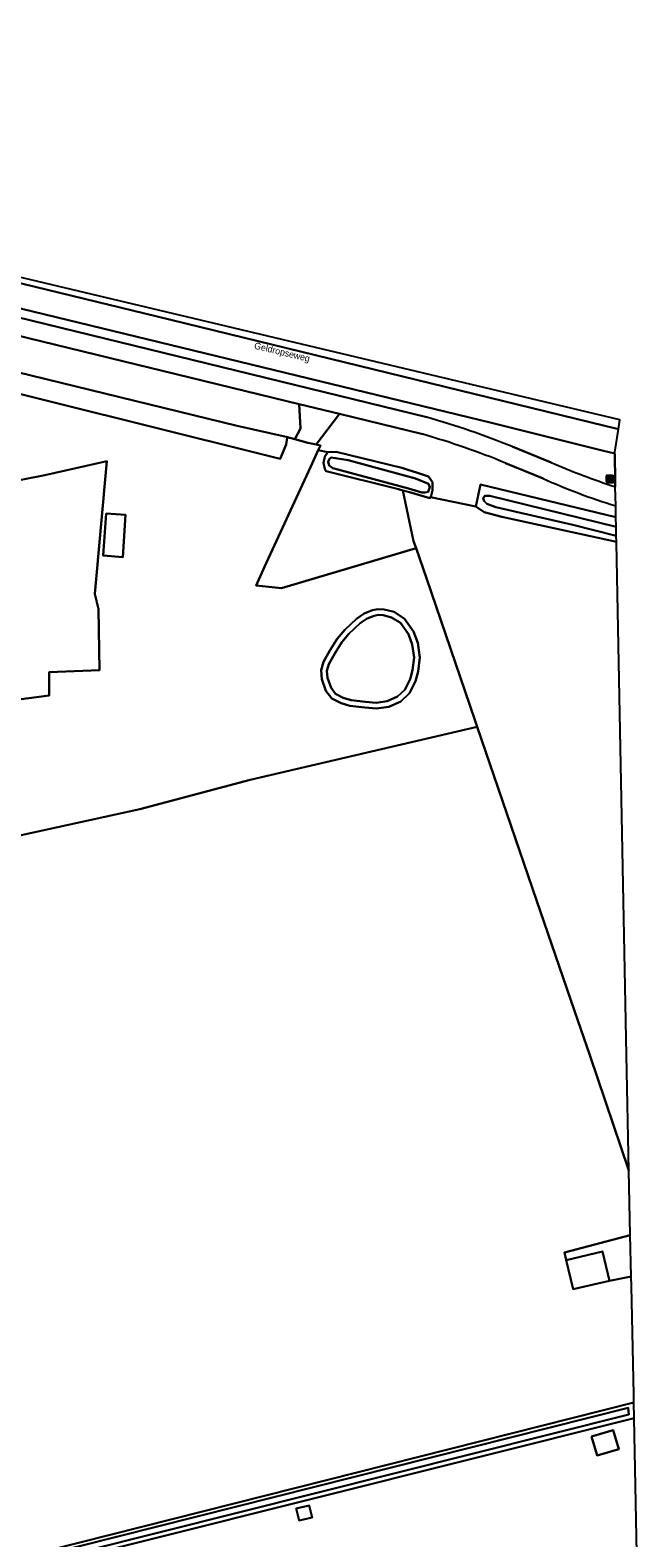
# Model space of a CAD drawing. Extents: x 163859 to 164644, y 379566 to 382155.
# Drawn here: x 164506.5 to 164599.2, y 381926.9 to 382155.2 of the extents above; entities that cross this region are included whole.
import ezdxf

# ---------------------------------------------------------------- set-up
doc = ezdxf.new("R2010")
doc.units = 0
for name, color, linetype in [('IMGEO_Berm_groen', 7, 'Continuous'), ('IMGEO_Erf', 7, 'Continuous'), ('IMGEO_Fietspad_gesloten', 7, 'Continuous'), ('IMGEO_Grasland_agrarisch', 7, 'Continuous'), ('IMGEO_Groenvoorziening', 7, 'Continuous'), ('IMGEO_Hek', 7, 'Continuous'), ('IMGEO_Lichtmast', 7, 'Continuous'), ('IMGEO_Loofbos', 7, 'Continuous'), ('IMGEO_Meer_plas_ven_vijver', 7, 'Continuous'), ('IMGEO_Oever', 7, 'Continuous'), ('IMGEO_Openbare_ruimte_label', 7, 'Continuous'), ('IMGEO_Pand', 7, 'Continuous'), ('IMGEO_Rijbaan_lokaal_onverhard', 7, 'Continuous'), ('IMGEO_Rijbaan_regionaal_gesloten', 7, 'Continuous'), ('IMGEO_Sloot', 7, 'Continuous'), ('IMGEO_Waterloop', 7, 'Continuous')]:
    doc.layers.add(name, color=color, linetype=linetype)

msp = doc.modelspace()

# ---------------------------------------------------------------- linework, layer by layer
at = {"layer": 'IMGEO_Berm_groen'}
msp.add_lwpolyline([(164595.15, 382087.13), (164595.08, 382091.04), (164595.08, 382090.8), (164595.15, 382087.13), (164595.15, 382087.13)], dxfattribs=at)
msp.add_lwpolyline([(164595.17, 382086.08), (164595.15, 382087.13), (164595.15, 382087.13)], close=True, dxfattribs=at)
at = {"layer": 'IMGEO_Erf'}
for points in [[(164503.08, 382032.86), (164523.11, 382037.28), (164539.85, 382041.68), (164574.25, 382049.73), (164573.89, 382050.78), (164566.54, 382072.23), (164564.98, 382076.78), (164544.61, 382070.72), (164540.74, 382071.15), (164542.03, 382073.97), (164548.98, 382089.07), (164550.17, 382091.64), (164550.48, 382092.32), (164549.84, 382092.47), (164548.6, 382092.76), (164546.64, 382093.3), (164545.32, 382093.66), (164545.44, 382093.5), (164545.3, 382092.48), (164544.39, 382090.34), (164522.31, 382095.81), (164513.2, 382098.08), (164500, 382101.39)], [(164489.95, 382084.16), (164508.72, 382087.84), (164518.12, 382089.97), (164516.34, 382069.87), (164516.85, 382067.53), (164517.02, 382058.31), (164509.39, 382058.02), (164509.38, 382054.47), (164503.23, 382053.66)]]:
    msp.add_lwpolyline(points, dxfattribs=at)
for points in [[(164518.05, 382082.03), (164520.97, 382081.81), (164520.54, 382075.41), (164517.58, 382075.67)], [(164560.15, 382067.52), (164561.64, 382067.12), (164563.24, 382066.11), (164564.61, 382064.19), (164565.24, 382062.43), (164565.55, 382060.24), (164565.31, 382058.13), (164564.88, 382056.65), (164563.98, 382054.81), (164562.65, 382053.56), (164560.86, 382052.78), (164558.98, 382052.5), (164557.22, 382052.66), (164554.95, 382052.89), (164553.62, 382053.32), (164552.22, 382054.03), (164551.32, 382055.2), (164550.69, 382056.96), (164550.58, 382058.29), (164550.97, 382059.58), (164551.9, 382061.3), (164553.04, 382063.06), (164554.17, 382064.43), (164555.97, 382066.11), (164557.14, 382066.89), (164558.36, 382067.4), (164559.18, 382067.55)], [(164597.57, 381966.47), (164597.43, 381972.77), (164587.47, 381970.11), (164587.73, 381968.98), (164593.24, 381970.26), (164594.27, 381965.83), (164597.57, 381966.47)]]:
    msp.add_lwpolyline(points, close=True, dxfattribs=at)
at = {"layer": 'IMGEO_Fietspad_gesloten'}
for points in [[(164351.79, 382149.02), (164352.26, 382146.27), (164358.29, 382144.8), (164362.68, 382143.73), (164380.09, 382139.4), (164383.9, 382138.46), (164391.87, 382136.53), (164462.95, 382119.3), (164479.66, 382115.15), (164500, 382110.11), (164547.27, 382098.59), (164553.37, 382097.11), (164566.02, 382094.03)], [(164566.61, 382096.62), (164500, 382112.87), (164480.06, 382117.73), (164432.23, 382129.4), (164397.28, 382137.92), (164390.72, 382139.52), (164384.51, 382141.04), (164380.7, 382141.97), (164360.68, 382146.85), (164351.79, 382149.02)], [(164585.46, 382089.75), (164579.54, 382092.17)], [(164578.55, 382089.67), (164584.23, 382087.34)], [(164595.23, 382083.2), (164595.17, 382086.08)]]:
    msp.add_lwpolyline(points, dxfattribs=at)
for centre, radius, start, end in [((164532.11, 381975.37), 126.06, 67.8989, 74.1185), ((164534.05, 381981.81), 116.68, 67.5816, 74.1012), ((164631.62, 382197.16), 116.91, 246.7456, 251.8362), ((164621.56, 382169.88), 90.59, 245.6621, 253.1015)]:
    msp.add_arc(centre, radius, start, end, dxfattribs=at)
at = {"layer": 'IMGEO_Grasland_agrarisch'}
for points in [[(164503.23, 382053.66), (164509.38, 382054.47), (164509.39, 382058.02), (164517.02, 382058.31), (164516.85, 382067.53), (164516.34, 382069.87), (164518.12, 382089.97), (164508.72, 382087.84), (164489.95, 382084.16)], [(164500, 381922.69), (164597.99, 381947.39), (164597.96, 381948.63), (164597.6, 381965), (164597.57, 381966.47), (164597.57, 381966.47), (164594.27, 381965.83), (164588.76, 381964.55), (164587.73, 381968.98), (164587.47, 381970.11), (164597.43, 381972.77), (164597.22, 381982.52), (164591.3, 382000), (164588.99, 382006.72), (164583.24, 382023.49), (164574.25, 382049.73), (164539.85, 382041.68), (164523.11, 382037.28), (164503.08, 382032.86)]]:
    msp.add_lwpolyline(points, dxfattribs=at)
at = {"layer": 'IMGEO_Groenvoorziening'}
for points in [[(164595.08, 382091.12), (164593.39, 382091.53), (164576.43, 382095.76), (164500, 382114.28), (164481.27, 382118.87), (164480.06, 382117.73), (164500, 382112.87), (164566.61, 382096.62)], [(164566.02, 382094.03), (164553.37, 382097.11), (164549.84, 382092.47), (164550.48, 382092.32), (164550.17, 382091.64), (164551.6, 382091.31), (164552.87, 382091.36), (164562.82, 382088.96), (164563.57, 382088.71), (164565.2, 382088.19), (164566.87, 382087.63), (164567.45, 382086.76), (164567.48, 382085.57), (164567.29, 382084.7), (164567.18, 382084.52), (164574.03, 382083.08), (164574.74, 382086.41), (164595.26, 382081.49), (164595.23, 382083.2)], [(164579.54, 382092.17), (164585.46, 382089.75)], [(164584.23, 382087.34), (164578.55, 382089.67)], [(164595.17, 382086.08), (164595.15, 382087.13), (164595.08, 382090.8), (164595.08, 382091.04), (164595.08, 382091.12)]]:
    msp.add_lwpolyline(points, dxfattribs=at)
for points in [[(164547.27, 382098.59), (164500, 382110.11), (164479.66, 382115.15), (164478.89, 382111.96), (164478.13, 382111.27), (164477.07, 382107.14), (164479.82, 382106.45), (164479.77, 382107.13), (164480.07, 382109.25), (164500, 382104.57), (164537.87, 382095.33), (164545.32, 382093.66), (164546.64, 382093.3), (164547.48, 382094.92)], [(164562.99, 382085.54), (164562.34, 382085.73), (164551.38, 382088.47), (164551.18, 382088.77), (164550.97, 382089.72), (164551.18, 382090.67), (164551.6, 382091.31), (164550.17, 382091.64), (164548.98, 382089.07), (164542.03, 382073.97), (164540.74, 382071.15), (164544.61, 382070.72), (164564.98, 382076.78), (164564.61, 382077.84)], [(164598.04, 381945.02), (164500, 381920.51), (164396.41, 381894.6), (164400.28, 381877.79), (164404.82, 381857.96), (164412.31, 381825.45), (164500, 381853.89), (164599.19, 381886.07)], [(164591.58, 381942.26), (164594.85, 381943.22), (164595.69, 381940.36), (164592.42, 381939.39)], [(164546.84, 381931.35), (164548.8, 381931.82), (164549.24, 381930.01), (164547.28, 381929.54)]]:
    msp.add_lwpolyline(points, close=True, dxfattribs=at)
for centre, radius, start, end in [((164532.11, 381975.37), 126.06, 67.8989, 74.1185), ((164534.05, 381981.81), 116.68, 67.5816, 74.1012), ((164631.62, 382197.16), 116.91, 246.7456, 251.8362), ((164621.56, 382169.88), 90.59, 245.6621, 253.1015)]:
    msp.add_arc(centre, radius, start, end, dxfattribs=at)
at = {"layer": 'IMGEO_Hek'}
for points in [[(164597.22, 381982.52), (164591.3, 382000)], [(164395.98, 381896.47), (164398.12, 381897.01), (164500, 381922.69), (164597.99, 381947.39)], [(164598.04, 381945.02), (164500, 381920.51), (164396.41, 381894.6)]]:
    msp.add_lwpolyline(points, dxfattribs=at)
at = {"layer": 'IMGEO_Lichtmast'}
for p, q in [((164593.81, 382086.9), (164593.81, 382087.7)), ((164593.81, 382087.7), (164593.81, 382086.9)), ((164593.91, 382087.8), (164594.69, 382087.8)), ((164594.69, 382087.8), (164593.91, 382087.8)), ((164593.92, 382086.83), (164593.92, 382087.63)), ((164593.92, 382087.63), (164593.92, 382086.83)), ((164594.02, 382087.73), (164594.8, 382087.73)), ((164594.8, 382087.73), (164594.02, 382087.73)), ((164594.79, 382087.7), (164594.79, 382086.9)), ((164594.79, 382086.9), (164594.79, 382087.7)), ((164594.9, 382087.63), (164594.9, 382086.83)), ((164594.9, 382086.83), (164594.9, 382087.63)), ((164594.69, 382086.8), (164593.91, 382086.8)), ((164593.91, 382086.8), (164594.69, 382086.8)), ((164594.8, 382086.73), (164594.02, 382086.73)), ((164594.02, 382086.73), (164594.8, 382086.73))]:
    msp.add_line(p, q, dxfattribs=at)
for points in [[(164594.22, 382087.67), (164594.38, 382087.67), (164594.38, 382086.92), (164594.22, 382086.92), (164594.22, 382087.67)], [(164594.33, 382087.6), (164594.49, 382087.6), (164594.49, 382086.85), (164594.33, 382086.85), (164594.33, 382087.6)]]:
    msp.add_lwpolyline(points, dxfattribs=at)
for centre, start, end in [((164593.91, 382087.7), 90, 180), ((164593.91, 382087.7), 90, 180), ((164593.91, 382086.9), 180, 270), ((164593.91, 382086.9), 180, 270), ((164594.02, 382087.63), 90, 180), ((164594.02, 382087.63), 90, 180), ((164594.02, 382086.83), 180, 270), ((164594.02, 382086.83), 180, 270), ((164594.69, 382087.7), 0, 90), ((164594.69, 382087.7), 360, 90), ((164594.69, 382086.9), 270, 0), ((164594.69, 382086.9), 270, 0), ((164594.8, 382087.63), 0, 90), ((164594.8, 382087.63), 360, 90), ((164594.8, 382086.83), 270, 0), ((164594.8, 382086.83), 270, 0)]:
    msp.add_arc(centre, 0.1, start, end, dxfattribs=at)
at = {"layer": 'IMGEO_Loofbos'}
msp.add_lwpolyline([(164597.22, 381982.52), (164596.85, 382000), (164595.34, 382077.59), (164595.34, 382077.74), (164595.34, 382077.74), (164577.96, 382081.55), (164575.32, 382082.24), (164574.03, 382083.08), (164567.18, 382084.52), (164567.08, 382084.38), (164564.87, 382085.01), (164564.01, 382085.25), (164562.99, 382085.54), (164564.61, 382077.84), (164564.98, 382076.78), (164566.54, 382072.23), (164573.89, 382050.78), (164574.25, 382049.73), (164583.24, 382023.49), (164588.99, 382006.72), (164591.3, 382000)], close=True, dxfattribs=at)
at = {"layer": 'IMGEO_Meer_plas_ven_vijver'}
msp.add_lwpolyline([(164564.45, 382058.3), (164564.67, 382060.23), (164564.38, 382062.22), (164563.83, 382063.78), (164562.63, 382065.46), (164561.28, 382066.31), (164560.02, 382066.65), (164559.24, 382066.68), (164558.61, 382066.56), (164557.56, 382066.12), (164556.51, 382065.42), (164554.81, 382063.83), (164553.74, 382062.54), (164552.66, 382060.85), (164551.78, 382059.24), (164551.46, 382058.2), (164551.55, 382057.15), (164552.1, 382055.62), (164552.79, 382054.72), (164553.96, 382054.14), (164555.13, 382053.75), (164557.3, 382053.53), (164558.96, 382053.38), (164560.61, 382053.62), (164562.17, 382054.3), (164563.27, 382055.34), (164564.07, 382056.96)], close=True, dxfattribs=at)
at = {"layer": 'IMGEO_Oever'}
for points in [[(164552.87, 382091.36), (164551.6, 382091.31), (164551.18, 382090.67), (164550.97, 382089.72), (164551.18, 382088.77), (164551.38, 382088.47), (164562.34, 382085.73), (164562.99, 382085.54), (164564.01, 382085.25), (164564.87, 382085.01), (164567.08, 382084.38), (164567.18, 382084.52), (164567.29, 382084.7), (164567.48, 382085.57), (164567.45, 382086.76), (164566.87, 382087.63), (164565.2, 382088.19), (164563.57, 382088.71), (164562.82, 382088.96)], [(164566.79, 382085.33), (164566.34, 382085.2), (164565.84, 382085.22), (164563.83, 382085.83), (164552.37, 382088.88), (164551.82, 382089.3), (164551.66, 382089.88), (164551.89, 382090.3), (164552.11, 382090.54), (164554.7, 382090.12), (164564.91, 382087.32), (164566.87, 382086.52), (164567.05, 382086.04)], [(164595.29, 382080), (164595.26, 382081.49), (164574.74, 382086.41), (164574.03, 382083.08), (164575.32, 382082.24), (164577.96, 382081.55), (164595.34, 382077.74), (164595.34, 382077.74), (164595.32, 382078.64), (164588.75, 382080.34), (164577.08, 382083), (164575.69, 382083.49), (164575.28, 382083.91), (164575.14, 382084.34), (164575.41, 382084.7), (164576.14, 382084.69)], [(164561.64, 382067.12), (164560.15, 382067.52), (164559.18, 382067.55), (164558.36, 382067.4), (164557.14, 382066.89), (164555.97, 382066.11), (164554.17, 382064.43), (164553.04, 382063.06), (164551.9, 382061.3), (164550.97, 382059.58), (164550.58, 382058.29), (164550.69, 382056.96), (164551.32, 382055.2), (164552.22, 382054.03), (164553.62, 382053.32), (164554.95, 382052.89), (164557.22, 382052.66), (164558.98, 382052.5), (164560.86, 382052.78), (164562.65, 382053.56), (164563.98, 382054.81), (164564.88, 382056.65), (164565.31, 382058.13), (164565.55, 382060.24), (164565.24, 382062.43), (164564.61, 382064.19), (164563.24, 382066.11)], [(164564.45, 382058.3), (164564.07, 382056.96), (164563.27, 382055.34), (164562.17, 382054.3), (164560.61, 382053.62), (164558.96, 382053.38), (164557.3, 382053.53), (164555.13, 382053.75), (164553.96, 382054.14), (164552.79, 382054.72), (164552.1, 382055.62), (164551.55, 382057.15), (164551.46, 382058.2), (164551.78, 382059.24), (164552.66, 382060.85), (164553.74, 382062.54), (164554.81, 382063.83), (164556.51, 382065.42), (164557.56, 382066.12), (164558.61, 382066.56), (164559.24, 382066.68), (164560.02, 382066.65), (164561.28, 382066.31), (164562.63, 382065.46), (164563.83, 382063.78), (164564.38, 382062.22), (164564.67, 382060.23)]]:
    msp.add_lwpolyline(points, close=True, dxfattribs=at)
for points in [[(164436.61, 381906.17), (164597.14, 381946.58), (164597.23, 381945.58), (164395.83, 381895.07)], [(164500, 381920.51), (164598.04, 381945.02), (164597.99, 381947.39), (164500, 381922.69)]]:
    msp.add_lwpolyline(points, dxfattribs=at)
at = {"layer": 'IMGEO_Pand'}
for points in [[(164518.05, 382082.03), (164517.58, 382075.67), (164520.54, 382075.41), (164520.97, 382081.81)], [(164593.24, 381970.26), (164587.73, 381968.98), (164588.76, 381964.55), (164594.27, 381965.83)], [(164591.58, 381942.26), (164592.42, 381939.39), (164595.69, 381940.36), (164594.85, 381943.22)], [(164546.84, 381931.35), (164547.28, 381929.54), (164549.24, 381930.01), (164548.8, 381931.82)]]:
    msp.add_lwpolyline(points, close=True, dxfattribs=at)
at = {"layer": 'IMGEO_Rijbaan_lokaal_onverhard'}
msp.add_lwpolyline([(164553.37, 382097.11), (164547.27, 382098.59), (164547.48, 382094.92), (164546.64, 382093.3), (164548.6, 382092.76), (164549.84, 382092.47)], close=True, dxfattribs=at)
at = {"layer": 'IMGEO_Rijbaan_regionaal_gesloten'}
for points in [[(164350.74, 382155.24), (164350.86, 382154.51), (164352.35, 382154.14), (164422.81, 382136.88), (164448.24, 382130.7), (164525.74, 382111.86), (164595.63, 382094.81), (164595.86, 382096.24), (164391.82, 382144.66), (164350.74, 382155.24)], [(164595.63, 382094.81), (164525.74, 382111.86), (164448.24, 382130.7), (164422.81, 382136.88), (164352.35, 382154.14), (164350.86, 382154.51), (164351.52, 382150.65), (164362.07, 382148.07), (164380.56, 382143.54), (164385.35, 382142.37), (164389.85, 382141.27), (164399.24, 382138.97), (164431.4, 382131.09), (164481.27, 382118.87), (164500, 382114.28), (164576.43, 382095.76), (164593.39, 382091.53), (164595.08, 382091.12), (164595.07, 382091.22), (164595.07, 382091.33), (164595.63, 382094.81)]]:
    msp.add_lwpolyline(points, dxfattribs=at)
at = {"layer": 'IMGEO_Sloot'}
msp.add_lwpolyline([(164595.32, 382078.64), (164595.29, 382080), (164576.14, 382084.69), (164575.41, 382084.7), (164575.14, 382084.34), (164575.28, 382083.91), (164575.69, 382083.49), (164577.08, 382083), (164588.75, 382080.34)], close=True, dxfattribs=at)
at = {"layer": 'IMGEO_Waterloop'}
for points in [[(164500, 382104.57), (164480.07, 382109.25), (164479.77, 382107.13), (164479.82, 382106.45), (164500, 382101.39), (164513.2, 382098.08), (164522.31, 382095.81), (164544.39, 382090.34), (164545.3, 382092.48), (164545.44, 382093.5), (164545.32, 382093.66), (164537.87, 382095.33)], [(164566.79, 382085.33), (164567.05, 382086.04), (164566.87, 382086.52), (164564.91, 382087.32), (164554.7, 382090.12), (164552.11, 382090.54), (164551.89, 382090.3), (164551.66, 382089.88), (164551.82, 382089.3), (164552.37, 382088.88), (164563.83, 382085.83), (164565.84, 382085.22), (164566.34, 382085.2)]]:
    msp.add_lwpolyline(points, close=True, dxfattribs=at)
msp.add_lwpolyline([(164395.83, 381895.07), (164597.23, 381945.58), (164597.14, 381946.58), (164436.61, 381906.17)], dxfattribs=at)

# ---------------------------------------------------------------- texts
at = {"layer": 'IMGEO_Openbare_ruimte_label'}
msp.add_text('Geldropseweg', height=1, rotation=346.3528, dxfattribs=at).set_placement((164540.38, 382107.02))

doc.saveas('drawing.dxf')
